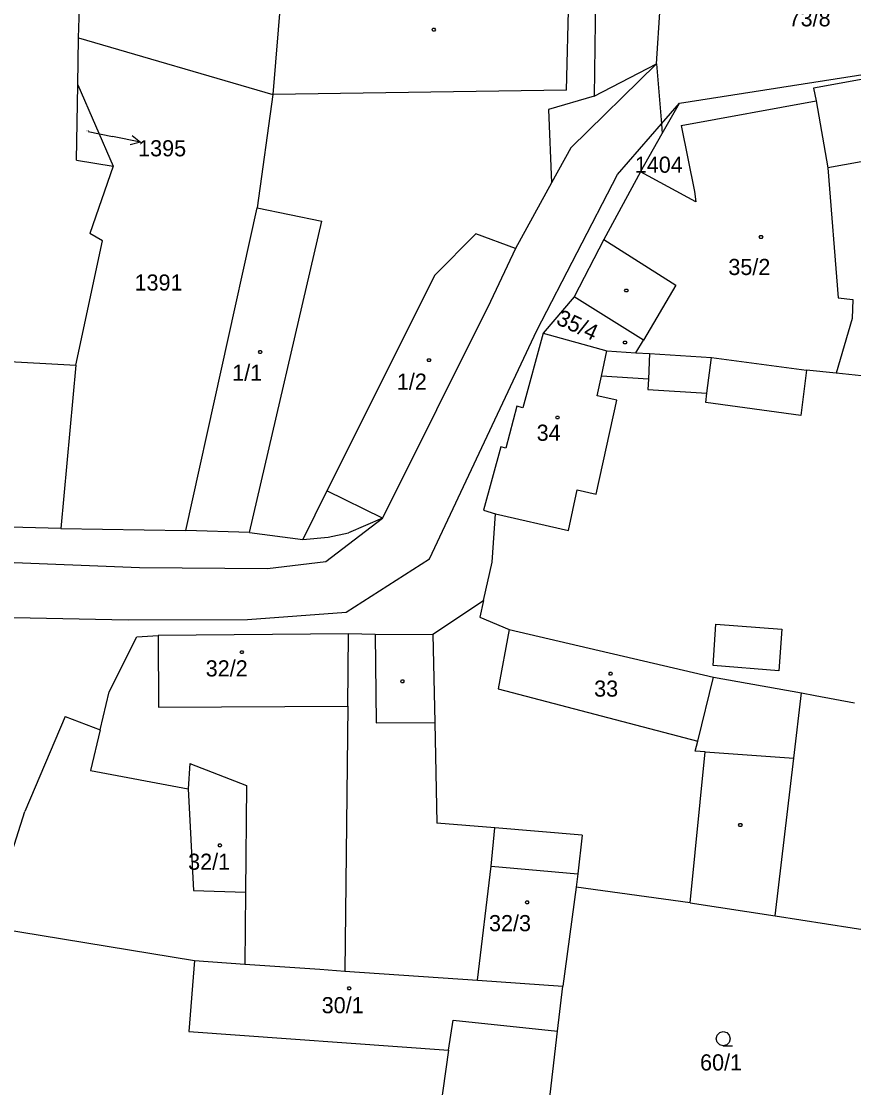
# Model space of a CAD drawing. Extents: x -852001 to -842497, y -1063614 to -1052182.
# Drawn here: x -844444 to -844356.3, y -1061526.1 to -1061413.7 of the extents above; entities that cross this region are included whole.
import ezdxf

# ---------------------------------------------------------------- set-up
doc = ezdxf.new("R2010")
doc.units = 0
for name, color, linetype in [('Default', 7, 'Continuous'), ('KN_HRANICE', 7, 'Continuous'), ('KN_KULTURY', 7, 'Continuous'), ('KN_PARCELY', 7, 'Continuous'), ('KN_SLUCKY', 7, 'Continuous')]:
    doc.layers.add(name, color=color, linetype=linetype)

# ---------------------------------------------------------------- blocks, each defined once
blk = doc.blocks.new('304')
at = {"layer": 'Default'}
blk.add_lwpolyline([(0, 0), (-0.38, 0.1), (-0.65, 0.37), (-0.75, 0.74), (-0.65, 1.11), (-0.38, 1.38), (-0.01, 1.48), (0.36, 1.38), (0.63, 1.11), (0.73, 0.73), (0.63, 0.35), (0.36, 0.08), (-0.02, -0.02), (0.98, -0.02)], dxfattribs=at)
blk = doc.blocks.new('NAHRADNI_SYMBOL')
at = {"layer": 'Default'}
blk.add_lwpolyline([(0.09, 0.15), (0.18, 0), (0.09, -0.15), (-0.09, -0.15), (-0.18, 0), (-0.09, 0.15), (0.09, 0.15)], dxfattribs=at)
blk = doc.blocks.new('10292')
at = {"layer": 'Default'}
blk.add_line((0, 3), (0, 0), dxfattribs=at)
blk.add_lwpolyline([(-0.5, 2), (0, 3), (0.5, 2)], dxfattribs=at)
blk = doc.blocks.new('402')
at = {"layer": 'Default'}
blk.add_lwpolyline([(0.09, 0.15), (0.18, 0), (0.09, -0.15), (-0.09, -0.15), (-0.18, 0), (-0.09, 0.15), (0.09, 0.15)], dxfattribs=at)

msp = doc.modelspace()

# ---------------------------------------------------------------- linework, layer by layer
at = {"layer": 'KN_HRANICE'}
for p, q in [((-844438.01, -1061415.47), (-844437.56, -1061398.83)), ((-844438.01, -1061415.47), (-844437.56, -1061398.83)), ((-844416.62, -1061410.01), (-844417.56, -1061421.43)), ((-844416.62, -1061410.01), (-844417.56, -1061421.43)), ((-844383.55, -1061410.22), (-844383.68, -1061421.62)), ((-844383.55, -1061410.22), (-844383.68, -1061421.62)), ((-844377.11, -1061418.19), (-844376.75, -1061412.24)), ((-844377.11, -1061418.19), (-844376.75, -1061412.24)), ((-844438.09, -1061420.42), (-844438.01, -1061415.47)), ((-844438.09, -1061420.42), (-844438.01, -1061415.47)), ((-844438.01, -1061415.47), (-844417.56, -1061421.43)), ((-844438.01, -1061415.47), (-844417.56, -1061421.43)), ((-844374.69, -1061422.36), (-844337.01, -1061416.42)), ((-844374.69, -1061422.36), (-844337.01, -1061416.42)), ((-844337.01, -1061416.42), (-844360.59, -1061420.77)), ((-844337.01, -1061416.42), (-844360.59, -1061420.77)), ((-844383.68, -1061421.62), (-844377.11, -1061418.19)), ((-844383.68, -1061421.62), (-844377.11, -1061418.19)), ((-844377.11, -1061418.19), (-844376.59, -1061424.54)), ((-844377.11, -1061418.19), (-844376.59, -1061424.54)), ((-844438.22, -1061428.35), (-844438.09, -1061420.42)), ((-844438.22, -1061428.35), (-844438.09, -1061420.42)), ((-844438.09, -1061420.42), (-844434.36, -1061428.99)), ((-844438.09, -1061420.42), (-844434.36, -1061428.99)), ((-844360.59, -1061420.77), (-844360.31, -1061422.11)), ((-844360.59, -1061420.77), (-844360.31, -1061422.11)), ((-844417.56, -1061421.43), (-844419.19, -1061433.37)), ((-844417.56, -1061421.43), (-844419.19, -1061433.37)), ((-844383.68, -1061421.62), (-844388.49, -1061423.02)), ((-844383.68, -1061421.62), (-844388.49, -1061423.02)), ((-844376.51, -1061425.55), (-844374.69, -1061422.36)), ((-844376.51, -1061425.55), (-844374.69, -1061422.36)), ((-844374.53, -1061424.7), (-844360.31, -1061422.11)), ((-844374.53, -1061424.7), (-844360.31, -1061422.11)), ((-844360.31, -1061422.11), (-844359.06, -1061429.16)), ((-844360.31, -1061422.11), (-844359.06, -1061429.16)), ((-844388.49, -1061423.02), (-844388.18, -1061430.75)), ((-844388.49, -1061423.02), (-844388.18, -1061430.75)), ((-844376.59, -1061424.54), (-844376.51, -1061425.55)), ((-844376.59, -1061424.54), (-844376.51, -1061425.55)), ((-844378.81, -1061429.57), (-844376.51, -1061425.55)), ((-844378.81, -1061429.57), (-844376.51, -1061425.55)), ((-844374.53, -1061424.7), (-844373.11, -1061431.65)), ((-844374.53, -1061424.7), (-844373.11, -1061431.65)), ((-844438.22, -1061428.35), (-844434.36, -1061428.99)), ((-844438.22, -1061428.35), (-844434.36, -1061428.99)), ((-844434.36, -1061428.99), (-844436.82, -1061436.08)), ((-844434.36, -1061428.99), (-844436.82, -1061436.08)), ((-844378.81, -1061429.57), (-844382.68, -1061436.7)), ((-844378.81, -1061429.57), (-844382.68, -1061436.7)), ((-844372.98, -1061432.73), (-844378.81, -1061429.57)), ((-844372.98, -1061432.73), (-844378.81, -1061429.57)), ((-844359.06, -1061429.16), (-844357.98, -1061442.87)), ((-844359.06, -1061429.16), (-844357.98, -1061442.87)), ((-844388.18, -1061430.75), (-844391.97, -1061437.66)), ((-844388.18, -1061430.75), (-844391.97, -1061437.66)), ((-844373.11, -1061431.65), (-844372.98, -1061432.73)), ((-844373.11, -1061431.65), (-844372.98, -1061432.73)), ((-844426.7, -1061467.38), (-844419.19, -1061433.37)), ((-844426.7, -1061467.38), (-844419.19, -1061433.37)), ((-844438.29, -1061449.97), (-844435.49, -1061436.86)), ((-844438.29, -1061449.97), (-844435.49, -1061436.86)), ((-844435.49, -1061436.86), (-844436.82, -1061436.08)), ((-844435.49, -1061436.86), (-844436.82, -1061436.08)), ((-844396.14, -1061436.12), (-844400.48, -1061440.48)), ((-844396.14, -1061436.12), (-844400.48, -1061440.48)), ((-844391.97, -1061437.66), (-844396.14, -1061436.12)), ((-844391.97, -1061437.66), (-844396.14, -1061436.12)), ((-844382.68, -1061436.7), (-844385.79, -1061442.75)), ((-844382.68, -1061436.7), (-844385.79, -1061442.75)), ((-844391.97, -1061437.66), (-844394.6, -1061443.25)), ((-844391.97, -1061437.66), (-844394.6, -1061443.25)), ((-844400.48, -1061440.48), (-844411.86, -1061463.19)), ((-844400.48, -1061440.48), (-844411.86, -1061463.19)), ((-844394.6, -1061443.25), (-844405.99, -1061466.08)), ((-844394.6, -1061443.25), (-844405.99, -1061466.08)), ((-844385.79, -1061442.75), (-844389.07, -1061446.6)), ((-844385.79, -1061442.75), (-844389.07, -1061446.6)), ((-844378.49, -1061447.34), (-844385.79, -1061442.75)), ((-844378.49, -1061447.34), (-844385.79, -1061442.75)), ((-844357.98, -1061442.87), (-844356.44, -1061443.03)), ((-844357.98, -1061442.87), (-844356.44, -1061443.03)), ((-844356.44, -1061443.03), (-844356.52, -1061445.06)), ((-844356.44, -1061443.03), (-844356.52, -1061445.06)), ((-844356.52, -1061445.06), (-844358.19, -1061450.8)), ((-844356.52, -1061445.06), (-844358.19, -1061450.8)), ((-844389.07, -1061446.6), (-844391.21, -1061454.46)), ((-844389.07, -1061446.6), (-844391.21, -1061454.46)), ((-844389.07, -1061446.6), (-844382.35, -1061448.45)), ((-844389.07, -1061446.6), (-844382.35, -1061448.45)), ((-844379.31, -1061448.65), (-844378.49, -1061447.34)), ((-844379.31, -1061448.65), (-844378.49, -1061447.34)), ((-844454.2, -1061449.07), (-844438.29, -1061449.97)), ((-844454.2, -1061449.07), (-844438.29, -1061449.97)), ((-844382.35, -1061448.45), (-844379.31, -1061448.65)), ((-844382.35, -1061448.45), (-844379.31, -1061448.65)), ((-844379.31, -1061448.65), (-844377.86, -1061448.74)), ((-844379.31, -1061448.65), (-844377.86, -1061448.74)), ((-844377.86, -1061448.74), (-844371.34, -1061449.16)), ((-844377.86, -1061448.74), (-844371.34, -1061449.16)), ((-844371.34, -1061449.16), (-844361.33, -1061450.48)), ((-844371.34, -1061449.16), (-844361.33, -1061450.48)), ((-844438.29, -1061449.97), (-844439.9, -1061467.16)), ((-844438.29, -1061449.97), (-844439.9, -1061467.16)), ((-844358.19, -1061450.8), (-844361.33, -1061450.48)), ((-844358.19, -1061450.8), (-844361.33, -1061450.48)), ((-844354.84, -1061451.14), (-844358.19, -1061450.8)), ((-844354.84, -1061451.14), (-844358.19, -1061450.8)), ((-844391.82, -1061454.3), (-844393.01, -1061458.7)), ((-844391.82, -1061454.3), (-844393.01, -1061458.7)), ((-844391.21, -1061454.46), (-844391.82, -1061454.3)), ((-844391.21, -1061454.46), (-844391.82, -1061454.3)), ((-844393.54, -1061458.56), (-844395.36, -1061465.26)), ((-844393.54, -1061458.56), (-844395.36, -1061465.26)), ((-844393.01, -1061458.7), (-844393.54, -1061458.56)), ((-844393.01, -1061458.7), (-844393.54, -1061458.56)), ((-844411.86, -1061463.19), (-844414.4, -1061468.34)), ((-844411.86, -1061463.19), (-844414.4, -1061468.34)), ((-844405.99, -1061466.08), (-844409.58, -1061467.62)), ((-844405.99, -1061466.08), (-844409.58, -1061467.62)), ((-844395.36, -1061465.26), (-844394.08, -1061465.63)), ((-844395.36, -1061465.26), (-844394.08, -1061465.63)), ((-844394.45, -1061470.71), (-844394.08, -1061465.63)), ((-844394.45, -1061470.71), (-844394.08, -1061465.63)), ((-844439.9, -1061467.16), (-844455.23, -1061466.77)), ((-844439.9, -1061467.16), (-844455.23, -1061466.77)), ((-844439.9, -1061467.16), (-844426.7, -1061467.38)), ((-844439.9, -1061467.16), (-844426.7, -1061467.38)), ((-844420.02, -1061467.61), (-844426.7, -1061467.38)), ((-844420.02, -1061467.61), (-844426.7, -1061467.38)), ((-844420.02, -1061467.61), (-844414.4, -1061468.34)), ((-844420.02, -1061467.61), (-844414.4, -1061468.34)), ((-844414.4, -1061468.34), (-844411.71, -1061468.09)), ((-844414.4, -1061468.34), (-844411.71, -1061468.09)), ((-844411.71, -1061468.09), (-844409.58, -1061467.62)), ((-844411.71, -1061468.09), (-844409.58, -1061467.62)), ((-844395.35, -1061474.75), (-844394.45, -1061470.71)), ((-844395.35, -1061474.75), (-844394.45, -1061470.71)), ((-844400.68, -1061478.33), (-844395.35, -1061474.75)), ((-844400.68, -1061478.33), (-844395.35, -1061474.75)), ((-844395.35, -1061474.75), (-844395.74, -1061476.53)), ((-844395.35, -1061474.75), (-844395.74, -1061476.53)), ((-844395.74, -1061476.53), (-844392.64, -1061477.84)), ((-844395.74, -1061476.53), (-844392.64, -1061477.84)), ((-844434.81, -1061484.41), (-844431.88, -1061478.59)), ((-844434.81, -1061484.41), (-844431.88, -1061478.59)), ((-844431.88, -1061478.59), (-844429.64, -1061478.44)), ((-844431.88, -1061478.59), (-844429.64, -1061478.44)), ((-844409.58, -1061478.29), (-844429.64, -1061478.44)), ((-844409.58, -1061478.29), (-844429.64, -1061478.44)), ((-844409.63, -1061485.89), (-844409.58, -1061478.29)), ((-844409.63, -1061485.89), (-844409.58, -1061478.29)), ((-844406.76, -1061478.35), (-844409.58, -1061478.29)), ((-844406.76, -1061478.35), (-844409.58, -1061478.29)), ((-844406.76, -1061478.35), (-844400.68, -1061478.33)), ((-844406.76, -1061478.35), (-844400.68, -1061478.33)), ((-844400.68, -1061478.33), (-844400.49, -1061487.61)), ((-844400.68, -1061478.33), (-844400.49, -1061487.61)), ((-844392.64, -1061477.84), (-844371.12, -1061482.83)), ((-844392.64, -1061477.84), (-844371.12, -1061482.83)), ((-844371.12, -1061482.83), (-844361.84, -1061484.51)), ((-844371.12, -1061482.83), (-844361.84, -1061484.51)), ((-844435.75, -1061488.39), (-844434.81, -1061484.41)), ((-844435.75, -1061488.39), (-844434.81, -1061484.41)), ((-844361.84, -1061484.51), (-844360.41, -1061484.77)), ((-844361.84, -1061484.51), (-844360.41, -1061484.77)), ((-844360.41, -1061484.77), (-844356.25, -1061485.54)), ((-844360.41, -1061484.77), (-844356.25, -1061485.54)), ((-844409.63, -1061485.89), (-844409.95, -1061513.82)), ((-844409.63, -1061485.89), (-844409.95, -1061513.82)), ((-844439.44, -1061487), (-844443.69, -1061496.99)), ((-844439.44, -1061487), (-844443.69, -1061496.99)), ((-844439.44, -1061487), (-844435.75, -1061488.39)), ((-844439.44, -1061487), (-844435.75, -1061488.39)), ((-844435.75, -1061488.39), (-844436.76, -1061492.67)), ((-844435.75, -1061488.39), (-844436.76, -1061492.67)), ((-844400.49, -1061487.61), (-844400.27, -1061498.23)), ((-844400.49, -1061487.61), (-844400.27, -1061498.23)), ((-844426.29, -1061491.95), (-844426.48, -1061494.63)), ((-844426.29, -1061491.95), (-844426.48, -1061494.63)), ((-844426.29, -1061491.95), (-844420.33, -1061494.26)), ((-844426.29, -1061491.95), (-844420.33, -1061494.26)), ((-844436.76, -1061492.67), (-844426.48, -1061494.63)), ((-844436.76, -1061492.67), (-844426.48, -1061494.63)), ((-844420.33, -1061494.26), (-844420.42, -1061505.52)), ((-844420.33, -1061494.26), (-844420.42, -1061505.52)), ((-844447.53, -1061509.13), (-844443.69, -1061496.99)), ((-844447.53, -1061509.13), (-844443.69, -1061496.99)), ((-844394.16, -1061498.74), (-844400.27, -1061498.23)), ((-844394.16, -1061498.74), (-844400.27, -1061498.23)), ((-844384.96, -1061499.51), (-844394.16, -1061498.74)), ((-844384.96, -1061499.51), (-844394.16, -1061498.74)), ((-844384.96, -1061499.51), (-844385.41, -1061503.58)), ((-844384.96, -1061499.51), (-844385.41, -1061503.58)), ((-844385.41, -1061503.58), (-844385.59, -1061504.98)), ((-844385.41, -1061503.58), (-844385.59, -1061504.98)), ((-844420.42, -1061505.52), (-844420.48, -1061513.08)), ((-844420.42, -1061505.52), (-844420.48, -1061513.08)), ((-844385.59, -1061504.98), (-844386.98, -1061515.43)), ((-844385.59, -1061504.98), (-844386.98, -1061515.43)), ((-844373.56, -1061506.62), (-844385.59, -1061504.98)), ((-844373.56, -1061506.62), (-844385.59, -1061504.98)), ((-844373.56, -1061506.62), (-844364.61, -1061507.99)), ((-844373.56, -1061506.62), (-844364.61, -1061507.99)), ((-844364.61, -1061507.99), (-844346.8, -1061510.8)), ((-844364.61, -1061507.99), (-844346.8, -1061510.8)), ((-844447.53, -1061509.13), (-844425.81, -1061512.7)), ((-844447.53, -1061509.13), (-844425.81, -1061512.7)), ((-844425.81, -1061512.7), (-844420.48, -1061513.08)), ((-844425.81, -1061512.7), (-844420.48, -1061513.08)), ((-844420.48, -1061513.08), (-844412.61, -1061513.63)), ((-844420.48, -1061513.08), (-844412.61, -1061513.63)), ((-844412.61, -1061513.63), (-844409.95, -1061513.82)), ((-844412.61, -1061513.63), (-844409.95, -1061513.82)), ((-844409.95, -1061513.82), (-844395.98, -1061514.79)), ((-844409.95, -1061513.82), (-844395.98, -1061514.79)), ((-844395.98, -1061514.79), (-844386.98, -1061515.43)), ((-844395.98, -1061514.79), (-844386.98, -1061515.43)), ((-844387.54, -1061520.17), (-844386.98, -1061515.43)), ((-844387.54, -1061520.17), (-844386.98, -1061515.43)), ((-844388.92, -1061531.86), (-844387.54, -1061520.17)), ((-844388.92, -1061531.86), (-844387.54, -1061520.17))]:
    msp.add_line(p, q, dxfattribs=at)
at = {"layer": 'KN_PARCELY'}
msp.add_line((-844437.02, -1061425.32), (-844434.44, -1061425.85), dxfattribs=at)
msp.add_line((-844437.02, -1061425.32), (-844434.44, -1061425.85), dxfattribs=at)
at = {"layer": 'KN_SLUCKY'}
for p, q in [((-844386.59, -1061420.96), (-844386.31, -1061409.93)), ((-844386.59, -1061420.96), (-844386.31, -1061409.93)), ((-844377.11, -1061418.19), (-844386.16, -1061427.05)), ((-844377.11, -1061418.19), (-844386.16, -1061427.05)), ((-844386.59, -1061420.96), (-844417.56, -1061421.43)), ((-844386.59, -1061420.96), (-844417.56, -1061421.43)), ((-844376.59, -1061424.54), (-844374.69, -1061422.36)), ((-844376.59, -1061424.54), (-844374.69, -1061422.36)), ((-844381.24, -1061429.88), (-844376.59, -1061424.54)), ((-844381.24, -1061429.88), (-844376.59, -1061424.54)), ((-844344.39, -1061426.55), (-844359.06, -1061429.16)), ((-844344.39, -1061426.55), (-844359.06, -1061429.16)), ((-844386.16, -1061427.05), (-844388.18, -1061430.75)), ((-844386.16, -1061427.05), (-844388.18, -1061430.75)), ((-844389.74, -1061446.32), (-844381.24, -1061429.88)), ((-844389.74, -1061446.32), (-844381.24, -1061429.88)), ((-844419.19, -1061433.37), (-844412.4, -1061434.79)), ((-844419.19, -1061433.37), (-844412.4, -1061434.79)), ((-844420.02, -1061467.61), (-844412.4, -1061434.79)), ((-844420.02, -1061467.61), (-844412.4, -1061434.79)), ((-844382.68, -1061436.7), (-844375.1, -1061441.54)), ((-844382.68, -1061436.7), (-844375.1, -1061441.54)), ((-844375.1, -1061441.54), (-844378.49, -1061447.34)), ((-844375.1, -1061441.54), (-844378.49, -1061447.34)), ((-844401.05, -1061470.37), (-844389.74, -1061446.32)), ((-844401.05, -1061470.37), (-844389.74, -1061446.32)), ((-844382.92, -1061451.13), (-844382.35, -1061448.45)), ((-844382.92, -1061451.13), (-844382.35, -1061448.45)), ((-844377.86, -1061448.74), (-844377.98, -1061451.42)), ((-844377.86, -1061448.74), (-844377.98, -1061451.42)), ((-844371.8, -1061452.92), (-844371.34, -1061449.16)), ((-844371.8, -1061452.92), (-844371.34, -1061449.16)), ((-844361.33, -1061450.48), (-844361.9, -1061455.27)), ((-844361.33, -1061450.48), (-844361.9, -1061455.27)), ((-844383.36, -1061453.19), (-844382.92, -1061451.13)), ((-844383.36, -1061453.19), (-844382.92, -1061451.13)), ((-844377.98, -1061451.42), (-844382.92, -1061451.13)), ((-844377.98, -1061451.42), (-844382.92, -1061451.13)), ((-844377.98, -1061451.42), (-844378.02, -1061452.52)), ((-844377.98, -1061451.42), (-844378.02, -1061452.52)), ((-844378.02, -1061452.52), (-844371.8, -1061452.92)), ((-844378.02, -1061452.52), (-844371.8, -1061452.92)), ((-844383.47, -1061463.57), (-844381.3, -1061453.64)), ((-844383.47, -1061463.57), (-844381.3, -1061453.64)), ((-844381.3, -1061453.64), (-844383.36, -1061453.19)), ((-844381.3, -1061453.64), (-844383.36, -1061453.19)), ((-844371.92, -1061453.88), (-844371.8, -1061452.92)), ((-844371.92, -1061453.88), (-844371.8, -1061452.92)), ((-844361.9, -1061455.27), (-844371.92, -1061453.88)), ((-844361.9, -1061455.27), (-844371.92, -1061453.88)), ((-844405.99, -1061466.08), (-844411.86, -1061463.19)), ((-844405.99, -1061466.08), (-844411.86, -1061463.19)), ((-844386.39, -1061467.4), (-844385.48, -1061463.11)), ((-844386.39, -1061467.4), (-844385.48, -1061463.11)), ((-844385.48, -1061463.11), (-844383.47, -1061463.57)), ((-844385.48, -1061463.11), (-844383.47, -1061463.57)), ((-844411.98, -1061470.66), (-844405.99, -1061466.08)), ((-844411.98, -1061470.66), (-844405.99, -1061466.08)), ((-844394.08, -1061465.63), (-844386.39, -1061467.4)), ((-844394.08, -1061465.63), (-844386.39, -1061467.4)), ((-844469.55, -1061469.78), (-844431.61, -1061471.3)), ((-844469.55, -1061469.78), (-844431.61, -1061471.3)), ((-844418.1, -1061471.4), (-844411.98, -1061470.66)), ((-844418.1, -1061471.4), (-844411.98, -1061470.66)), ((-844409.83, -1061476.01), (-844401.05, -1061470.37)), ((-844409.83, -1061476.01), (-844401.05, -1061470.37)), ((-844431.61, -1061471.3), (-844418.1, -1061471.4)), ((-844431.61, -1061471.3), (-844418.1, -1061471.4)), ((-844468.98, -1061476.02), (-844432.78, -1061476.81)), ((-844468.98, -1061476.02), (-844432.78, -1061476.81)), ((-844420.2, -1061476.77), (-844409.83, -1061476.01)), ((-844420.2, -1061476.77), (-844409.83, -1061476.01)), ((-844432.78, -1061476.81), (-844420.2, -1061476.77)), ((-844432.78, -1061476.81), (-844420.2, -1061476.77)), ((-844371.15, -1061481.62), (-844370.87, -1061477.27)), ((-844371.15, -1061481.62), (-844370.87, -1061477.27)), ((-844370.87, -1061477.27), (-844363.93, -1061477.78)), ((-844370.87, -1061477.27), (-844363.93, -1061477.78)), ((-844429.64, -1061478.44), (-844429.6, -1061486.01)), ((-844429.64, -1061478.44), (-844429.6, -1061486.01)), ((-844406.76, -1061478.35), (-844406.66, -1061487.65)), ((-844406.76, -1061478.35), (-844406.66, -1061487.65)), ((-844392.64, -1061477.84), (-844393.8, -1061484.06)), ((-844392.64, -1061477.84), (-844393.8, -1061484.06)), ((-844363.93, -1061477.78), (-844364.22, -1061482.18)), ((-844363.93, -1061477.78), (-844364.22, -1061482.18)), ((-844364.22, -1061482.18), (-844371.15, -1061481.62)), ((-844364.22, -1061482.18), (-844371.15, -1061481.62)), ((-844372.78, -1061489.61), (-844371.12, -1061482.83)), ((-844372.78, -1061489.61), (-844371.12, -1061482.83)), ((-844393.8, -1061484.06), (-844372.78, -1061489.61)), ((-844393.8, -1061484.06), (-844372.78, -1061489.61)), ((-844362.65, -1061491.38), (-844361.84, -1061484.51)), ((-844362.65, -1061491.38), (-844361.84, -1061484.51)), ((-844429.6, -1061486.01), (-844409.63, -1061485.89)), ((-844429.6, -1061486.01), (-844409.63, -1061485.89)), ((-844406.66, -1061487.65), (-844400.49, -1061487.61)), ((-844406.66, -1061487.65), (-844400.49, -1061487.61)), ((-844373.06, -1061490.65), (-844372.78, -1061489.61)), ((-844373.06, -1061490.65), (-844372.78, -1061489.61)), ((-844373.56, -1061506.62), (-844371.98, -1061490.72)), ((-844373.56, -1061506.62), (-844371.98, -1061490.72)), ((-844371.98, -1061490.72), (-844373.06, -1061490.65)), ((-844371.98, -1061490.72), (-844373.06, -1061490.65)), ((-844371.98, -1061490.72), (-844362.65, -1061491.38)), ((-844371.98, -1061490.72), (-844362.65, -1061491.38)), ((-844364.61, -1061507.99), (-844362.65, -1061491.38)), ((-844364.61, -1061507.99), (-844362.65, -1061491.38)), ((-844426.48, -1061494.63), (-844425.9, -1061505.34)), ((-844426.48, -1061494.63), (-844425.9, -1061505.34)), ((-844394.54, -1061502.78), (-844394.16, -1061498.74)), ((-844394.54, -1061502.78), (-844394.16, -1061498.74)), ((-844395.98, -1061514.79), (-844394.54, -1061502.78)), ((-844395.98, -1061514.79), (-844394.54, -1061502.78)), ((-844394.54, -1061502.78), (-844385.41, -1061503.58)), ((-844394.54, -1061502.78), (-844385.41, -1061503.58)), ((-844425.9, -1061505.34), (-844420.42, -1061505.52)), ((-844425.9, -1061505.34), (-844420.42, -1061505.52)), ((-844425.81, -1061512.7), (-844426.4, -1061520.2)), ((-844425.81, -1061512.7), (-844426.4, -1061520.2)), ((-844399.03, -1061522.17), (-844398.54, -1061519)), ((-844399.03, -1061522.17), (-844398.54, -1061519)), ((-844398.54, -1061519), (-844387.54, -1061520.17)), ((-844398.54, -1061519), (-844387.54, -1061520.17)), ((-844426.4, -1061520.2), (-844399.03, -1061522.17)), ((-844426.4, -1061520.2), (-844399.03, -1061522.17)), ((-844399.03, -1061522.17), (-844401.68, -1061540.59)), ((-844399.03, -1061522.17), (-844401.68, -1061540.59))]:
    msp.add_line(p, q, dxfattribs=at)

# ---------------------------------------------------------------- block references
at = {"layer": 'KN_KULTURY'}
for name, p in [('402', (-844400.59, -1061414.6)), ('402', (-844400.59, -1061414.6)), ('402', (-844366.11, -1061436.46)), ('402', (-844366.11, -1061436.46)), ('402', (-844380.3, -1061442.09)), ('402', (-844380.3, -1061442.09)), ('NAHRADNI_SYMBOL', (-844380.44, -1061447.58)), ('NAHRADNI_SYMBOL', (-844380.44, -1061447.58)), ('402', (-844418.87, -1061448.58)), ('402', (-844418.87, -1061448.58)), ('402', (-844401.09, -1061449.43)), ('402', (-844401.09, -1061449.43)), ('402', (-844387.55, -1061455.48)), ('402', (-844387.55, -1061455.48)), ('402', (-844420.82, -1061480.21)), ('402', (-844420.82, -1061480.21)), ('402', (-844381.96, -1061482.48)), ('402', (-844381.96, -1061482.48)), ('402', (-844403.89, -1061483.28)), ('402', (-844403.89, -1061483.28)), ('402', (-844368.29, -1061498.43)), ('402', (-844368.29, -1061498.43)), ('402', (-844423.12, -1061500.58)), ('402', (-844423.12, -1061500.58)), ('402', (-844390.76, -1061506.58)), ('402', (-844390.76, -1061506.58)), ('402', (-844409.5, -1061515.64)), ('402', (-844409.5, -1061515.64)), ('304', (-844370.08, -1061521.69)), ('304', (-844370.08, -1061521.69))]:
    msp.add_blockref(name, p, dxfattribs=at)
at = {"layer": 'KN_PARCELY', "rotation": -101.65332999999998}
msp.add_blockref('10292', (-844434.44, -1061425.85), dxfattribs=at)
msp.add_blockref('10292', (-844434.44, -1061425.85), dxfattribs=at)

# ---------------------------------------------------------------- texts
at = {"layer": 'KN_PARCELY'}
for s, height, p in [('73/8', 1.7, (-844363.2, -1061414.25)), ('73/8', 1.7, (-844363.2, -1061414.25)), ('1395', 0.1, (-844437.22, -1061425.32)), ('1395', 0.1, (-844437.22, -1061425.32)), ('1395', 1.7, (-844431.74, -1061427.95)), ('1395', 1.7, (-844431.74, -1061427.95)), ('1404', 1.7, (-844379.41, -1061429.68)), ('1404', 1.7, (-844379.41, -1061429.68)), ('35/2', 1.7, (-844369.55, -1061440.46)), ('35/2', 1.7, (-844369.55, -1061440.46)), ('1391', 1.7, (-844432.12, -1061442.1)), ('1391', 1.7, (-844432.12, -1061442.1)), ('1/1', 1.7, (-844421.83, -1061451.61)), ('1/1', 1.7, (-844421.83, -1061451.61)), ('1/2', 1.7, (-844404.48, -1061452.55)), ('1/2', 1.7, (-844404.48, -1061452.55)), ('34', 1.7, (-844389.75, -1061457.93)), ('34', 1.7, (-844389.75, -1061457.93)), ('32/2', 1.7, (-844424.62, -1061482.77)), ('32/2', 1.7, (-844424.62, -1061482.77)), ('33', 1.7, (-844383.69, -1061484.9)), ('33', 1.7, (-844383.69, -1061484.9)), ('32/1', 1.7, (-844426.47, -1061503.15)), ('32/1', 1.7, (-844426.47, -1061503.15)), ('32/3', 1.7, (-844394.77, -1061509.62)), ('32/3', 1.7, (-844394.77, -1061509.62)), ('30/1', 1.7, (-844412.4, -1061518.27)), ('30/1', 1.7, (-844412.4, -1061518.27)), ('60/1', 1.7, (-844372.53, -1061524.3)), ('60/1', 1.7, (-844372.53, -1061524.3))]:
    msp.add_text(s, height=height, dxfattribs=at).set_placement(p)
msp.add_text('35/4', height=1.7, rotation=335.409, dxfattribs=at).set_placement((-844387.81, -1061445.58))
msp.add_text('35/4', height=1.7, rotation=335.409, dxfattribs=at).set_placement((-844387.81, -1061445.58))

doc.saveas('drawing.dxf')
